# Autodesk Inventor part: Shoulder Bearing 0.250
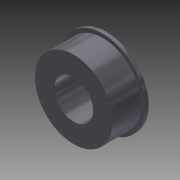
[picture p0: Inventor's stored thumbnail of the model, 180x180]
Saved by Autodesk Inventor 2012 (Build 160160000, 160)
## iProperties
Created: 2011-05
Part Number: Shoulder Bearing 0.250
Document SubType Name: Modeling
Designer: Alex
Density: 7.84 g/cm^3
Material: Steel, High Strength Low Alloy
Mass: 4.09675 g
Surface Area: 5.62061 cm^2
Volume: 0.522544 cm^3
Author: Alex
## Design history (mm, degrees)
sketch "Sketch1"
  geometry: C1 r 6.947 at (0, 0); 1 further point
  constraints: 1 centre point, 1 coincident
  dimensions: "d0" = 13.8938 diameter of C1
extrude "Extrusion1" new body sketch "Sketch1" distance "d3" = 0.5842; taper "d4" = 0 deg
sketch "Sketch2"
  geometry: C1 r 6.947 at (0, 0) reference; C2 r 6.35 at (0, 0)
  constraints: 1 centre point, 1 coincident
  dimensions: "d5" = 12.7 diameter of C2
extrude "Extrusion2" join sketch "Sketch2" distance "d6" = 4.7625; taper "d7" = 0 deg
sketch "Sketch3"
  geometry: C1 r 6.35 at (0, 0) reference; 1 further point
  constraints: 1 coincident
hole "Hole1" sketch "Sketch3" at (0, 0) diameter "d8" = 6.35; stored, may be unused: countersink angle "d12" = 82 deg, drill point angle "d14" = 118 deg; dims "d9" = 19.05, "d10" = 9.525, "d11" = 6.35, "d13" = 25.4
body "Solid1"
